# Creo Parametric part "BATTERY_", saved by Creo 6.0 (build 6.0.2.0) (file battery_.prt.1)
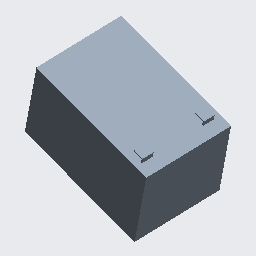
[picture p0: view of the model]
Units: Inch lbm Second (Pro/E Default); INCH, POUND, SECS

Created from: INLBS_PART_SOLID.PRT

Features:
  1. datum plane "RIGHT"
  2. datum plane "TOP"
  3. datum plane "FRONT"
  4. coordinate system
  5. sketch "Sketch 1"
  6. extrusion "Extrude 1"
  7. sketch "Sketch 2"
  8. extrusion "Extrude 2"
  9. sketch "Sketch 3"
  10. extrusion "Extrude 3"

Surfaces: 18 plane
